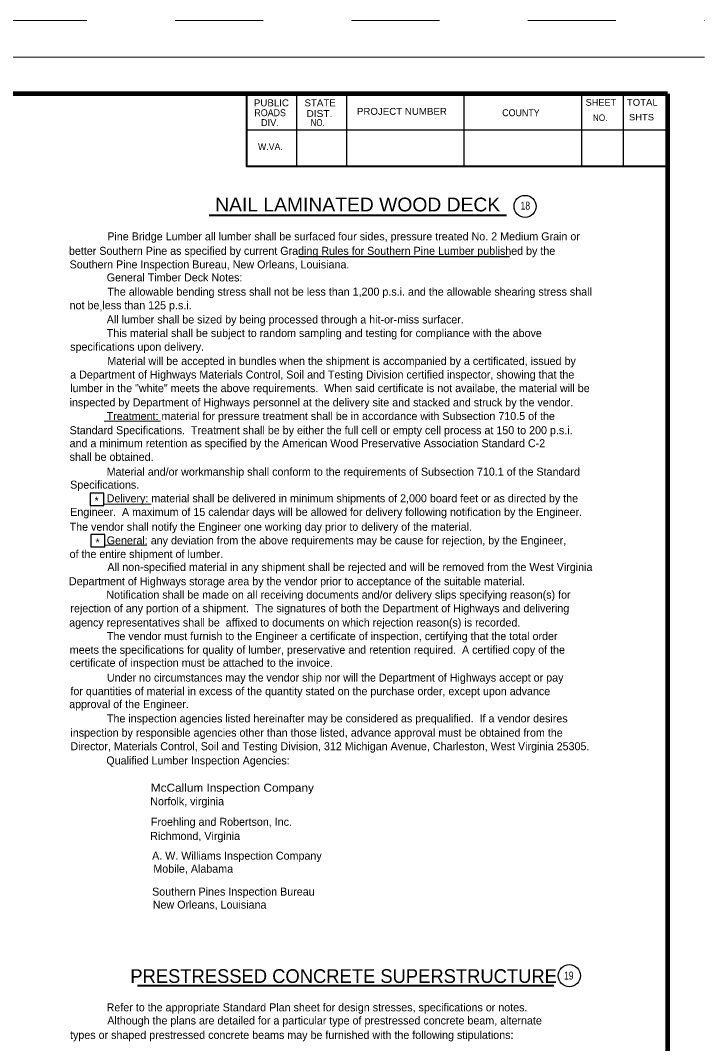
# Model space of a CAD drawing. Extents: x -2.94 to 3.45, y 0.57 to 4.
# Drawn here: x 2.678 to 3.454, y 2.377 to 3.538 of the extents above; entities that cross this region are included whole.
import ezdxf
from ezdxf.enums import TextEntityAlignment as Align

# ---------------------------------------------------------------- set-up
doc = ezdxf.new("R2010")
doc.units = 0
doc.header["$LTSCALE"] = 0.0036
doc.linetypes.add('LONG_DASHED', pattern=[7.5, 6, -1.5])
doc.layers.add('1', color=7, linetype='Continuous', lineweight=13)
doc.layers.add('3', color=7, linetype='Continuous', lineweight=25)

msp = doc.modelspace()

# ---------------------------------------------------------------- linework, layer by layer
at = {"layer": '1', "linetype": 'LONG_DASHED'}
msp.add_line((0.45325, 3.53825), (3.45375, 3.53825), dxfattribs=at)
at = {"layer": '1'}
msp.add_line((0.45325, 3.496583), (3.45375, 3.496583), dxfattribs=at)
at = {"layer": '1', "lineweight": 158}
for q in [(0.599333, 3.455), (3.411833, 1.705)]:
    msp.add_line((3.411833, 3.455), q, dxfattribs=at)
at = {"layer": '1', "lineweight": 25}
for p, q in [((2.990917, 3.455), (2.990917, 3.373)), ((3.0475, 3.455), (3.0475, 3.373)), ((3.180917, 3.455), (3.180917, 3.373)), ((3.314167, 3.455), (3.314167, 3.373)), ((3.3615, 3.455), (3.3615, 3.373)), ((2.93425, 3.414083), (3.411833, 3.414083))]:
    msp.add_line(p, q, dxfattribs=at)
at = {"layer": '1', "lineweight": 40}
msp.add_lwpolyline([(2.93425, 3.455), (2.93425, 3.373), (3.411833, 3.373)], dxfattribs=at)
at = {"layer": '3', "lineweight": 40}
for p, q in [((2.891833, 3.317417), (3.22925, 3.317417)), ((2.810417, 2.442833), (3.28275, 2.442833))]:
    msp.add_line(p, q, dxfattribs=at)
at = {"layer": '3'}
msp.add_line((2.99325, 3.270417), (3.232583, 3.270417), dxfattribs=at)
at = {"layer": '3', "lineweight": 13}
for p, q in [((2.772917, 3.083417), (2.83675, 3.083417)), ((2.772917, 2.98925), (2.82625, 2.98925)), ((2.774333, 2.942917), (2.821333, 2.942917))]:
    msp.add_line(p, q, dxfattribs=at)
at = {"layer": '3'}
for points in [[(2.756833, 3.001833), (2.756833, 2.987583), (2.772417, 2.987583), (2.772417, 3.001833)], [(2.757833, 2.955), (2.757833, 2.94075), (2.773417, 2.94075), (2.773417, 2.955)]]:
    msp.add_lwpolyline(points, close=True, dxfattribs=at)
for centre in [(3.25025, 3.32725), (3.300417, 2.454167)]:
    msp.add_circle(centre, 0.0125, dxfattribs=at)

# ---------------------------------------------------------------- texts
at = {"layer": '1'}
for s, height, width, p in [('PUBLIC', 0.007834, 1.05, (2.9625, 3.440833)), ('STATE', 0.007834, 1.05, (3.01775, 3.440833)), ('TOTAL', 0.007751, 1.05, (3.383167, 3.441417)), ('ROADS', 0.007918, 0.95, (2.961042, 3.429583)), ('PROJECT NUMBER', 0.007834, 1.05, (3.1105, 3.431167)), ('COUNTY', 0.007918, 0.95, (3.2455, 3.429583)), ('DIST.', 0.007834, 1.1, (3.016958, 3.428667)), ('NO.', 0.007834, 0.85, (3.015, 3.418417)), ('NO.', 0.007334, 0.95, (3.335417, 3.42425)), ('SHTS', 0.007251, 1.1, (3.38225, 3.424833)), ('W.VA.', 0.007834, 0.95, (2.961333, 3.391083))]:
    msp.add_text(s, height=height, dxfattribs=dict(at, width=width)).set_placement(p, align=Align.CENTER)
for s, height, p in [('SHEET', 0.007751, (3.336208, 3.441417)), ('DIV.', 0.007834, (2.960792, 3.418417))]:
    msp.add_text(s, height=height, dxfattribs=at).set_placement(p, align=Align.CENTER)
at = {"layer": '3'}
for s, height, width, p in [('NAIL LAMINATED WOOD DECK', 0.01558, 1.05, (3.060333, 3.321583)), ('18', 0.009083, 0.8, (3.2505, 3.323583)), ('19', 0.009083, 0.8, (3.299792, 2.449667))]:
    msp.add_text(s, height=height, dxfattribs=dict(at, width=width)).set_placement(p, align=Align.CENTER)
for s, p in [('Pine Bridge Lumber all lumber shall be surfaced four sides, pressure treated No. 2 Medium Grain or ', (2.776333, 3.288667)), ('better Southern Pine as specified by current Grading Rules for Southern Pine Lumber published by the', (2.732833, 3.27225)), ('Southern Pine Inspection Bureau, New Orleans, Louisiana.', (2.733583, 3.256833)), ('General Timber Deck Notes:', (2.775667, 3.242083)), ('The allowable bending stress shall not be less than 1,200 p.s.i. and the allowable shearing stress shall', (2.776417, 3.225917)), ('not be less than 125 p.s.i.', (2.733583, 3.2105)), ('All lumber shall be sized by being processed through a hit-or-miss surfacer.', (2.775667, 3.194333)), ('This material shall be subject to random sampling and testing for compliance with the above ', (2.775667, 3.178917)), ('specifications upon delivery.', (2.73425, 3.163417)), ('Material will be accepted in bundles when the shipment is accompanied by a certificated, issued by ', (2.776417, 3.14725)), ('a Department of Highways Materials Control, Soil and Testing Division certified inspector, showing that the', (2.73425, 3.131833)), ('lumber in the "white" meets the above requirements.  When said certificate is not availabe, the material will be ', (2.73425, 3.116417)), ('inspected by Department of Highways personnel at the delivery site and stacked and struck by the vendor.', (2.733583, 3.10025)), ('Treatment: material for pressure treatment shall be in accordance with Subsection 710.5 of the', (2.775667, 3.08475)), ('Standard Specifications.  Treatment shall be by either the full cell or empty cell process at 150 to 200 p.s.i.', (2.733583, 3.068667)), ('and a minimum retention as specified by the American Wood Preservative Association Standard C-2 ', (2.733583, 3.053917)), ('shall be obtained.', (2.733583, 3.038417)), ('Material and/or workmanship shall conform to the requirements of Subsection 710.1 of the Standard', (2.775667, 3.021583)), ('Specifications.', (2.73425, 3.006833)), ('*', (2.761917, 2.98875)), ('Delivery: material shall be delivered in minimum shipments of 2,000 board feet or as directed by the ', (2.775667, 2.991417)), ('Engineer.  A maximum of 15 calendar days will be allowed for delivery following notification by the Engineer.', (2.73425, 2.975917)), ('The vendor shall notify the Engineer one working day prior to delivery of the material.', (2.733583, 2.959083)), ('*', (2.762917, 2.941333)), ('General: any deviation from the above requirements may be cause for rejection, by the Engineer,', (2.775667, 2.943667)), ('of the entire shipment of lumber.', (2.733583, 2.928167)), ('All non-specified material in any shipment shall be rejected and will be removed from the West Virginia', (2.776417, 2.913417)), ('Department of Highways storage area by the vendor prior to acceptance of the suitable material.', (2.732833, 2.89725)), ('Notification shall be made on all receiving documents and/or delivery slips specifying reason(s) for', (2.77525, 2.882)), ('rejection of any portion of a shipment.  The signatures of both the Department of Highways and delivering ', (2.7345, 2.866583)), ('agency representatives shall be  affixed to documents on which rejection reason(s) is recorded.', (2.733083, 2.850417)), ('The vendor must furnish to the Engineer a certificate of inspection, certifying that the total order', (2.775917, 2.835)), ('meets the specifications for quality of lumber, preservative and retention required.  A certified copy of the  ', (2.73375, 2.8195)), ('certificate of inspection must be attached to the invoice.', (2.73375, 2.80475)), ('Under no circumstances may the vendor ship nor will the Department of Highways accept or pay', (2.775917, 2.787917)), ('for quantities of material in excess of the quantity stated on the purchase order, except upon advance', (2.7345, 2.7725)), ('approval of the Engineer.', (2.733083, 2.75775)), ('The inspection agencies listed hereinafter may be considered as prequalified.  If a vendor desires', (2.775917, 2.741583)), ('inspection by responsible agencies other than those listed, advance approval must be obtained from the ', (2.7345, 2.725417)), ('Director, Materials Control, Soil and Testing Division, 312 Michigan Avenue, Charleston, West Virginia 25305.', (2.7345, 2.71)), ('Qualified Lumber Inspection Agencies:', (2.77525, 2.693833)), ('Norfolk, virginia', (2.825083, 2.6475)), ('Froehling and Robertson, Inc.', (2.825833, 2.62425)), ('Richmond, Virginia', (2.825, 2.608167)), ('A. W. Williams Inspection Company', (2.827167, 2.58575)), ('Mobile, Alabama', (2.828583, 2.571)), ('Southern Pines Inspection Bureau', (2.827167, 2.545)), ('New Orleans, Louisiana', (2.827917, 2.53025)), ('Refer to the appropriate Standard Plan sheet for design stresses, specifications or notes.', (2.775583, 2.413667)), ('Although the plans are detailed for a particular type of prestressed concrete beam, alternate', (2.776333, 2.39875)), ('types or shaped prestressed concrete beams may be furnished with the following stipulations:', (2.734083, 2.382333))]:
    msp.add_text(s, height=0.009083, dxfattribs=at).set_placement(p)
for s, width, p in [(',', 0.8, (2.76775, 3.209417)), ('McCallum Inspection Company', 1.1, (2.82575, 2.662917))]:
    msp.add_text(s, height=0.009083, dxfattribs=dict(at, width=width)).set_placement(p)
msp.add_text('PRESTRESSED CONCRETE SUPERSTRUCTURE', height=0.01558, dxfattribs=at).set_placement((3.044375, 2.445917), align=Align.CENTER)

doc.saveas('drawing.dxf')
